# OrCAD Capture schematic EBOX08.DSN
size C
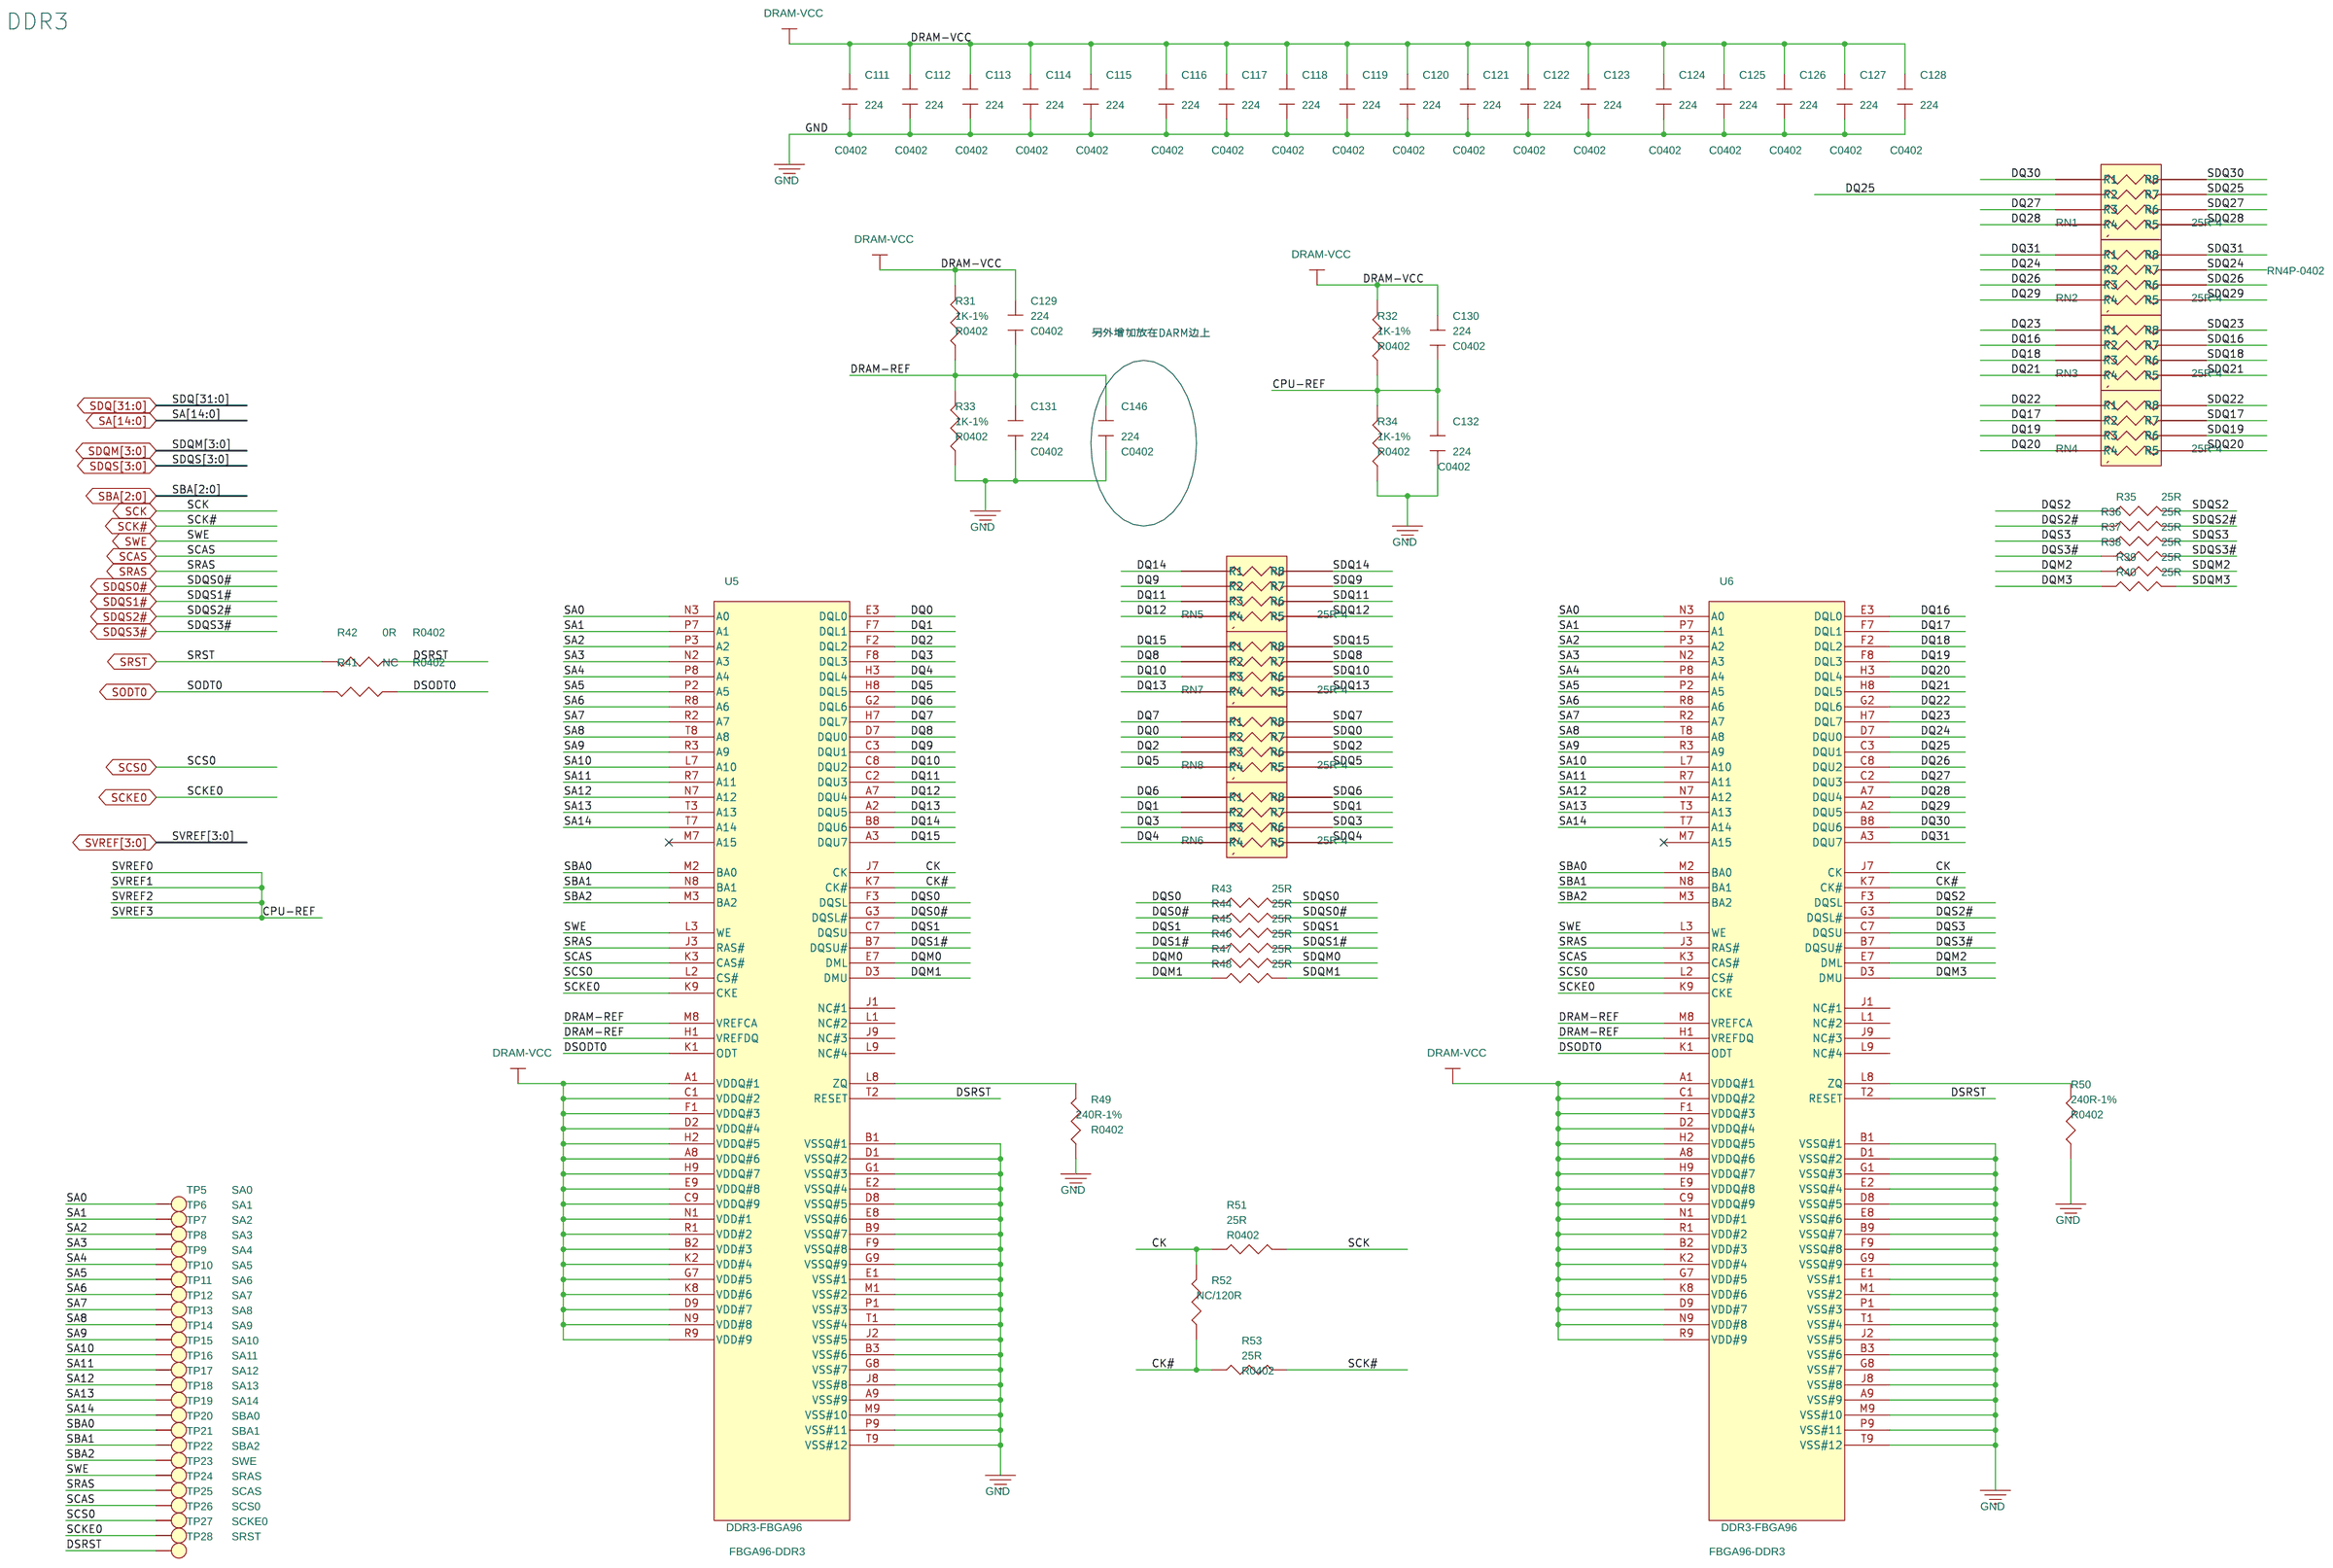
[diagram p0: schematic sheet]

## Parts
C111  224  [C0402]
C112  224  [C0402]
C113  224  [C0402]
C114  224  [C0402]
C115  224  [C0402]
C116  224  [C0402]
C117  224  [C0402]
C118  224  [C0402]
C119  224  [C0402]
C120  224  [C0402]
C121  224  [C0402]
C122  224  [C0402]
C123  224  [C0402]
C124  224  [C0402]
C125  224  [C0402]
C126  224  [C0402]
C127  224  [C0402]
C128  224  [C0402]
C129  224  [C0402]
C130  224  [C0402]
C131  224  [C0402]
C132  224  [C0402]
C146  224  [C0402]
R31  1K-1%  [R0402]
R32  1K-1%  [R0402]
R33  1K-1%  [R0402]
R34  1K-1%  [R0402]
R35  25R  [R0402]
R36  25R  [R0402]
R37  25R  [R0402]
R38  25R  [R0402]
R39  25R  [R0402]
R40  25R  [R0402]
R41  NC  [R0402]
R42  0R  [R0402]
R43  25R  [R0402]
R44  25R  [R0402]
R45  25R  [R0402]
R46  25R  [R0402]
R47  25R  [R0402]
R48  25R  [R0402]
R49  240R-1%  [R0402]
R50  240R-1%  [R0402]
R51  25R  [R0402]
R52  NC/120R  [R0402]
R53  25R  [R0402]
RN1  25R*4  [RN4P-0402]
RN2  25R*4  [RN4P-0402]
RN3  25R*4  [RN4P-0402]
RN4  25R*4  [RN4P-0402]
RN5  25R*4  [RN4P-0402]
RN6  25R*4  [RN4P-0402]
RN7  25R*4  [RN4P-0402]
RN8  25R*4  [RN4P-0402]
TP5  SA0  [TP_SMD050]
TP6  SA1  [TP_SMD050]
TP7  SA2  [TP_SMD050]
TP8  SA3  [TP_SMD050]
TP9  SA4  [TP_SMD050]
TP10  SA5  [TP_SMD050]
TP11  SA6  [TP_SMD050]
TP12  SA7  [TP_SMD050]
TP13  SA8  [TP_SMD050]
TP14  SA9  [TP_SMD050]
TP15  SA10  [TP_SMD050]
TP16  SA11  [TP_SMD050]
TP17  SA12  [TP_SMD050]
TP18  SA13  [TP_SMD050]
TP19  SA14  [TP_SMD050]
TP20  SBA0  [TP_SMD050]
TP21  SBA1  [TP_SMD050]
TP22  SBA2  [TP_SMD050]
TP23  SWE  [TP_SMD050]
TP24  SRAS  [TP_SMD050]
TP25  SCAS  [TP_SMD050]
TP26  SCS0  [TP_SMD050]
TP27  SCKE0  [TP_SMD050]
TP28  SRST  [TP_SMD050]
U5  DDR3-FBGA96  [FBGA96-DDR3]
U6  DDR3-FBGA96  [FBGA96-DDR3]

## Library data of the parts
C111-C132 C146 = CAP
R31-R53 = R1_0805
RN1-RN8 = R-PACK4_1
TP5-TP28 = T_POINT_R
U5 U6 = DDR3_0

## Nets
GND: C111.2 C112.2 C113.2 C114.2 C115.2 C116.2 C117.2 C118.2 C119.2 C120.2 C121.2 C122.2 C123.2 C124.2 C125.2 C126.2 C127.2 C128.2 C131.2 C132.2 C146.2 R33.1 R34.1 R49.1 R50.1 U5.A9(VSS#9) U5.B1(VSSQ#1) U5.B3(VSS#6) U5.B9(VSSQ#7) U5.D1(VSSQ#2) U5.D8(VSSQ#5) U5.E1(VSS#1) U5.E2(VSSQ#4) U5.E8(VSSQ#6) U5.F9(VSSQ#8) U5.G1(VSSQ#3) U5.G8(VSS#7) U5.G9(VSSQ#9) U5.J2(VSS#5) U5.J8(VSS#8) U5.M1(VSS#2) U5.M9(VSS#10) U5.P1(VSS#3) U5.P9(VSS#11) U5.T1(VSS#4) U5.T9(VSS#12) U6.A9(VSS#9) U6.B1(VSSQ#1) U6.B3(VSS#6) U6.B9(VSSQ#7) U6.D1(VSSQ#2) U6.D8(VSSQ#5) U6.E1(VSS#1) U6.E2(VSSQ#4) U6.E8(VSSQ#6) U6.F9(VSSQ#8) U6.G1(VSSQ#3) U6.G8(VSS#7) U6.G9(VSSQ#9) U6.J2(VSS#5) U6.J8(VSS#8) U6.M1(VSS#2) U6.M9(VSS#10) U6.P1(VSS#3) U6.P9(VSS#11) U6.T1(VSS#4) U6.T9(VSS#12)
CK: R51.1 R52.2 U5.J7(CK) U6.J7(CK)
CK#: R52.1 R53.1 U5.K7(CK#) U6.K7(CK#)
DQ0: RN8.2(R2) U5.E3(DQL0)
DQ1: RN6.2(R2) U5.F7(DQL1)
DQ2: RN8.3(R3) U5.F2(DQL2)
DQ3: RN6.3(R3) U5.F8(DQL3)
DQ4: RN6.4(R4) U5.H3(DQL4)
DQ5: RN8.4(R4) U5.H8(DQL5)
DQ6: RN6.1(R1) U5.G2(DQL6)
DQ7: RN8.1(R1) U5.H7(DQL7)
DQ8: RN7.2(R2) U5.D7(DQU0)
DQ9: RN5.2(R2) U5.C3(DQU1)
DQ10: RN7.3(R3) U5.C8(DQU2)
DQ11: RN5.3(R3) U5.C2(DQU3)
DQ12: RN5.4(R4) U5.A7(DQU4)
DQ13: RN7.4(R4) U5.A2(DQU5)
DQ14: RN5.1(R1) U5.B8(DQU6)
DQ15: RN7.1(R1) U5.A3(DQU7)
DQ16: RN3.2(R2) U6.E3(DQL0)
DQ17: RN4.2(R2) U6.F7(DQL1)
DQ18: RN3.3(R3) U6.F2(DQL2)
DQ19: RN4.3(R3) U6.F8(DQL3)
DQ20: RN4.4(R4) U6.H3(DQL4)
DQ21: RN3.4(R4) U6.H8(DQL5)
DQ22: RN4.1(R1) U6.G2(DQL6)
DQ23: RN3.1(R1) U6.H7(DQL7)
DQ24: RN2.2(R2) U6.D7(DQU0)
DQ25: RN1.2(R2) U6.C3(DQU1)
DQ26: RN2.3(R3) U6.C8(DQU2)
DQ27: RN1.3(R3) U6.C2(DQU3)
DQ28: RN1.4(R4) U6.A7(DQU4)
DQ29: RN2.4(R4) U6.A2(DQU5)
DQ30: RN1.1(R1) U6.B8(DQU6)
DQ31: RN2.1(R1) U6.A3(DQU7)
DQM0: R47.1 U5.E7(DML)
DQM1: R48.1 U5.D3(DMU)
DQM2: R39.1 U6.E7(DML)
DQM3: R40.1 U6.D3(DMU)
DQS0: R43.1 U5.F3(DQSL)
DQS0#: R44.1 U5.G3(DQSL#)
DQS1: R45.1 U5.C7(DQSU)
DQS1#: R46.1 U5.B7(DQSU#)
DQS2: R35.1 U6.F3(DQSL)
DQS2#: R36.1 U6.G3(DQSL#)
DQS3: R37.1 U6.C7(DQSU)
DQS3#: R38.1 U6.B7(DQSU#)
DRAM-REF: C129.2 C131.1 C146.1 R31.1 R33.2 U5.H1(VREFDQ) U5.M8(VREFCA) U6.H1(VREFDQ) U6.M8(VREFCA)
DRAM-VCC: C111.1 C112.1 C113.1 C114.1 C115.1 C116.1 C117.1 C118.1 C119.1 C120.1 C121.1 C122.1 C123.1 C124.1 C125.1 C126.1 C127.1 C128.1 C129.1 C130.1 R31.2 R32.2 U5.A1(VDDQ#1) U5.A8(VDDQ#6) U5.B2(VDD#3) U5.C1(VDDQ#2) U5.C9(VDDQ#9) U5.D2(VDDQ#4) U5.D9(VDD#7) U5.E9(VDDQ#8) U5.F1(VDDQ#3) U5.G7(VDD#5) U5.H2(VDDQ#5) U5.H9(VDDQ#7) U5.K2(VDD#4) U5.K8(VDD#6) U5.N1(VDD#1) U5.N9(VDD#8) U5.R1(VDD#2) U5.R9(VDD#9) U6.A1(VDDQ#1) U6.A8(VDDQ#6) U6.B2(VDD#3) U6.C1(VDDQ#2) U6.C9(VDDQ#9) U6.D2(VDDQ#4) U6.D9(VDD#7) U6.E9(VDDQ#8) U6.F1(VDDQ#3) U6.G7(VDD#5) U6.H2(VDDQ#5) U6.H9(VDDQ#7) U6.K2(VDD#4) U6.K8(VDD#6) U6.N1(VDD#1) U6.N9(VDD#8) U6.R1(VDD#2) U6.R9(VDD#9)
DSODT0: R41.1 U5.K1(ODT) U6.K1(ODT)
DSRST: R42.1 TP28.1(TP) U5.T2(RESET) U6.T2(RESET)
SA0: TP5.1(TP) U5.N3(A0) U6.N3(A0)
SA1: TP6.1(TP) U5.P7(A1) U6.P7(A1)
SA2: TP7.1(TP) U5.P3(A2) U6.P3(A2)
SA3: TP8.1(TP) U5.N2(A3) U6.N2(A3)
SA4: TP9.1(TP) U5.P8(A4) U6.P8(A4)
SA5: TP10.1(TP) U5.P2(A5) U6.P2(A5)
SA6: TP11.1(TP) U5.R8(A6) U6.R8(A6)
SA7: TP12.1(TP) U5.R2(A7) U6.R2(A7)
SA8: TP13.1(TP) U5.T8(A8) U6.T8(A8)
SA9: TP14.1(TP) U5.R3(A9) U6.R3(A9)
SA10: TP15.1(TP) U5.L7(A10) U6.L7(A10)
SA11: TP16.1(TP) U5.R7(A11) U6.R7(A11)
SA12: TP17.1(TP) U5.N7(A12) U6.N7(A12)
SA13: TP18.1(TP) U5.T3(A13) U6.T3(A13)
SA14: TP19.1(TP) U5.T7(A14) U6.T7(A14)
SBA0: TP20.1(TP) U5.M2(BA0) U6.M2(BA0)
SBA1: TP21.1(TP) U5.N8(BA1) U6.N8(BA1)
SBA2: TP22.1(TP) U5.M3(BA2) U6.M3(BA2)
SCAS: TP25.1(TP) U5.K3(CAS#) U6.K3(CAS#)
SCK: R51.2
SCK#: R53.2
SCKE0: TP27.1(TP) U5.K9(CKE) U6.K9(CKE)
SCS0: TP26.1(TP) U5.L2(CS#) U6.L2(CS#)
SDQ0: RN8.7(R7)
SDQ1: RN6.7(R7)
SDQ2: RN8.6(R6)
SDQ3: RN6.6(R6)
SDQ4: RN6.5(R5)
SDQ5: RN8.5(R5)
SDQ6: RN6.8(R8)
SDQ7: RN8.8(R8)
SDQ8: RN7.7(R7)
SDQ9: RN5.7(R7)
SDQ10: RN7.6(R6)
SDQ11: RN5.6(R6)
SDQ12: RN5.5(R5)
SDQ13: RN7.5(R5)
SDQ14: RN5.8(R8)
SDQ15: RN7.8(R8)
SDQ16: RN3.7(R7)
SDQ17: RN4.7(R7)
SDQ18: RN3.6(R6)
SDQ19: RN4.6(R6)
SDQ20: RN4.5(R5)
SDQ21: RN3.5(R5)
SDQ22: RN4.8(R8)
SDQ23: RN3.8(R8)
SDQ24: RN2.7(R7)
SDQ25: RN1.7(R7)
SDQ26: RN2.6(R6)
SDQ27: RN1.6(R6)
SDQ28: RN1.5(R5)
SDQ29: RN2.5(R5)
SDQ30: RN1.8(R8)
SDQ31: RN2.8(R8)
SDQM0: R47.2
SDQM1: R48.2
SDQM2: R39.2
SDQM3: R40.2
SDQS0: R43.2
SDQS0#: R44.2
SDQS1: R45.2
SDQS1#: R46.2
SDQS2: R35.2
SDQS2#: R36.2
SDQS3: R37.2
SDQS3#: R38.2
SODT0: R41.2
SRAS: TP24.1(TP) U5.J3(RAS#) U6.J3(RAS#)
SRST: R42.2
SVREF0: C130.2 C132.1 R32.1 R34.2
SWE: TP23.1(TP) U5.L3(WE) U6.L3(WE)
N07736: R49.2 U5.L8(ZQ)
N08048: R50.2 U6.L8(ZQ)

Not connected (* = marked no-connect by the designer): U5 J1(NC#1) J9(NC#3) L1(NC#2) L9(NC#4) M7(A15)*; U6 J1(NC#1) J9(NC#3) L1(NC#2) L9(NC#4) M7(A15)*

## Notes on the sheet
- DDR3
- 另外增加放在DARM边上
